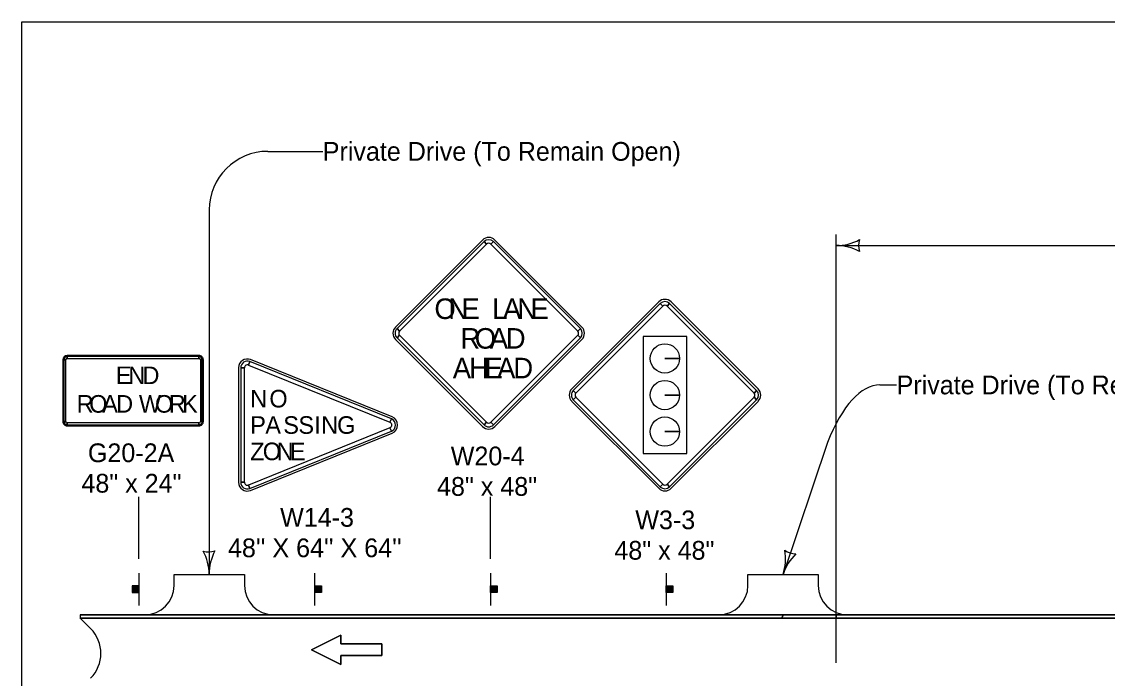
# Model space of a CAD drawing. Extents: x -2134934 to -2127057, y -2139046 to -2137036.
# Drawn here: x -2134934 to -2134008, y -2137596 to -2137036 of the extents above; entities that cross this region are included whole.
import ezdxf

# ---------------------------------------------------------------- set-up
doc = ezdxf.new("R2010")
doc.units = 0
for name, color, linetype in [('Barrier', 7, 'Continuous'), ('BridgeSuperStructureExisting', 7, 'Continuous'), ('Default', 7, 'Continuous'), ('DsnShtPlotIdentification', 7, 'Continuous'), ('DsnShtPlotShape', 7, 'Continuous')]:
    doc.layers.add(name, color=color, linetype=linetype)

msp = doc.modelspace()

# ---------------------------------------------------------------- linework, layer by layer
at = {"layer": 'Barrier'}
for p, q in [((-2134541.21, -2137222.31), (-2134615.45, -2137296.56)), ((-2134539.88, -2137223.64), (-2134537.67, -2137225.85)), ((-2134534.14, -2137225.85), (-2134531.93, -2137223.64)), ((-2134456.35, -2137296.56), (-2134530.6, -2137222.31)), ((-2134390.77, -2137275.12), (-2134465.02, -2137349.37)), ((-2134389.45, -2137276.45), (-2134387.24, -2137278.66)), ((-2134383.7, -2137278.66), (-2134381.49, -2137276.45)), ((-2134305.92, -2137349.37), (-2134380.17, -2137275.12)), ((-2134611.92, -2137300.09), (-2134614.13, -2137297.88)), ((-2134457.68, -2137297.88), (-2134459.89, -2137300.09)), ((-2134615.45, -2137307.16), (-2134541.21, -2137381.41)), ((-2134614.13, -2137305.84), (-2134611.92, -2137303.63)), ((-2134530.6, -2137381.41), (-2134456.35, -2137307.16)), ((-2134459.89, -2137303.63), (-2134457.68, -2137305.84)), ((-2134899.41, -2137324.64), (-2134899.41, -2137377.14)), ((-2134898.48, -2137324.64), (-2134896.91, -2137324.64)), ((-2134783.16, -2137320.89), (-2134895.66, -2137320.89)), ((-2134895.66, -2137323.39), (-2134895.66, -2137321.82)), ((-2134783.16, -2137321.82), (-2134783.16, -2137323.39)), ((-2134781.91, -2137324.64), (-2134780.35, -2137324.64)), ((-2134779.41, -2137377.14), (-2134779.41, -2137324.64)), ((-2134740.97, -2137329.01), (-2134739.8, -2137326.11)), ((-2134618.27, -2137373.25), (-2134739.1, -2137324.37)), ((-2134373.06, -2137323.34), (-2134385.56, -2137323.34)), ((-2134385.56, -2137323.34), (-2134373.06, -2137323.34)), ((-2134749.41, -2137331.32), (-2134749.41, -2137429.07)), ((-2134747.53, -2137331.32), (-2134744.41, -2137331.32)), ((-2134461.48, -2137352.9), (-2134463.69, -2137350.69)), ((-2134463.69, -2137358.65), (-2134461.48, -2137356.44)), ((-2134373.06, -2137354.59), (-2134385.56, -2137354.59)), ((-2134385.56, -2137354.59), (-2134373.06, -2137354.59)), ((-2134307.25, -2137350.69), (-2134309.45, -2137352.9)), ((-2134309.45, -2137356.44), (-2134307.25, -2137358.65)), ((-2134465.02, -2137359.98), (-2134390.77, -2137434.22)), ((-2134380.17, -2137434.22), (-2134305.92, -2137359.98)), ((-2134618.98, -2137374.98), (-2134620.15, -2137377.88)), ((-2134896.91, -2137377.14), (-2134898.48, -2137377.14)), ((-2134895.66, -2137379.95), (-2134895.66, -2137378.39)), ((-2134895.66, -2137380.89), (-2134783.16, -2137380.89)), ((-2134783.16, -2137378.39), (-2134783.16, -2137379.95)), ((-2134780.35, -2137377.14), (-2134781.91, -2137377.14)), ((-2134620.15, -2137382.52), (-2134618.98, -2137385.41)), ((-2134537.67, -2137377.87), (-2134539.88, -2137380.08)), ((-2134531.93, -2137380.08), (-2134534.14, -2137377.87)), ((-2134739.1, -2137436.03), (-2134618.27, -2137387.15)), ((-2134373.06, -2137385.84), (-2134385.56, -2137385.84)), ((-2134385.56, -2137385.84), (-2134373.06, -2137385.84)), ((-2134744.41, -2137429.07), (-2134747.53, -2137429.07)), ((-2134387.24, -2137430.69), (-2134389.45, -2137432.9)), ((-2134381.49, -2137432.9), (-2134383.7, -2137430.69)), ((-2134739.8, -2137434.29), (-2134740.97, -2137431.39))]:
    msp.add_line(p, q, dxfattribs=at)
for points in [[(-2134539.88, -2137223.64), (-2134614.13, -2137297.88), (-2134611.92, -2137300.09), (-2134537.67, -2137225.85), (-2134539.88, -2137223.64)], [(-2134457.68, -2137297.88), (-2134531.93, -2137223.64), (-2134534.14, -2137225.85), (-2134459.89, -2137300.09), (-2134457.68, -2137297.88)], [(-2134389.45, -2137276.45), (-2134463.69, -2137350.69), (-2134461.48, -2137352.9), (-2134387.24, -2137278.66), (-2134389.45, -2137276.45)], [(-2134307.25, -2137350.69), (-2134381.49, -2137276.45), (-2134383.7, -2137278.66), (-2134309.45, -2137352.9), (-2134307.25, -2137350.69)], [(-2134614.13, -2137305.84), (-2134539.88, -2137380.08), (-2134537.67, -2137377.87), (-2134611.92, -2137303.63), (-2134614.13, -2137305.84)], [(-2134531.93, -2137380.08), (-2134457.68, -2137305.84), (-2134459.89, -2137303.63), (-2134534.14, -2137377.87), (-2134531.93, -2137380.08)], [(-2134366.74, -2137304.73), (-2134404.2, -2137304.73), (-2134404.2, -2137404.62), (-2134366.74, -2137404.62), (-2134366.74, -2137304.73)], [(-2134898.48, -2137324.64), (-2134898.48, -2137377.14), (-2134896.91, -2137377.14), (-2134896.91, -2137324.64), (-2134898.48, -2137324.64)], [(-2134783.16, -2137321.82), (-2134895.66, -2137321.82), (-2134895.66, -2137323.39), (-2134783.16, -2137323.39), (-2134783.16, -2137321.82)], [(-2134780.35, -2137377.14), (-2134780.35, -2137324.64), (-2134781.91, -2137324.64), (-2134781.91, -2137377.14), (-2134780.35, -2137377.14)], [(-2134618.98, -2137374.98), (-2134739.8, -2137326.11), (-2134740.97, -2137329.01), (-2134620.15, -2137377.88), (-2134618.98, -2137374.98)], [(-2134747.53, -2137331.32), (-2134747.53, -2137429.07), (-2134744.41, -2137429.07), (-2134744.41, -2137331.32), (-2134747.53, -2137331.32)], [(-2134463.69, -2137358.65), (-2134389.45, -2137432.9), (-2134387.24, -2137430.69), (-2134461.48, -2137356.44), (-2134463.69, -2137358.65)], [(-2134381.49, -2137432.9), (-2134307.25, -2137358.65), (-2134309.45, -2137356.44), (-2134383.7, -2137430.69), (-2134381.49, -2137432.9)], [(-2134895.66, -2137379.95), (-2134783.16, -2137379.95), (-2134783.16, -2137378.39), (-2134895.66, -2137378.39), (-2134895.66, -2137379.95)], [(-2134739.8, -2137434.29), (-2134618.98, -2137385.41), (-2134620.15, -2137382.52), (-2134740.97, -2137431.39), (-2134739.8, -2137434.29)]]:
    msp.add_lwpolyline(points, close=True, dxfattribs=at)
for centre in [(-2134385.56, -2137323.34), (-2134385.56, -2137354.59), (-2134385.56, -2137385.84)]:
    msp.add_circle(centre, 12.5, dxfattribs=at)
for centre, radius, start, end in [((-2134535.9, -2137227.61), 7.5, 44.99999, 134.99974), ((-2134535.9, -2137227.61), 5.62, 44.99999, 134.99974), ((-2134535.9, -2137227.61), 2.5, 44.99999, 134.99974), ((-2134385.47, -2137280.43), 7.5, 44.99999, 134.99974), ((-2134385.47, -2137280.43), 5.62, 44.99999, 134.99974), ((-2134385.47, -2137280.43), 2.5, 44.99999, 134.99974), ((-2134610.15, -2137301.86), 7.5, 134.99974, 224.99995), ((-2134610.15, -2137301.86), 5.62, 134.99974, 224.99995), ((-2134610.15, -2137301.86), 2.5, 134.99974, 224.99995), ((-2134461.66, -2137301.86), 2.5, 315.00016, 44.9998), ((-2134461.66, -2137301.86), 5.62, 315.00016, 44.9998), ((-2134461.66, -2137301.86), 7.5, 315.00016, 44.9998), ((-2134895.66, -2137324.64), 3.75, 90.00021, 179.99985), ((-2134895.66, -2137324.64), 2.81, 90.00021, 179.99985), ((-2134895.66, -2137324.64), 1.25, 90.00021, 179.99985), ((-2134783.16, -2137324.64), 3.75, 0, 90.00021), ((-2134783.16, -2137324.64), 2.81, 0, 90.00021), ((-2134783.16, -2137324.64), 1.25, 0, 90.00021), ((-2134741.91, -2137331.32), 7.5, 67.97571, 179.99985), ((-2134741.91, -2137331.32), 5.62, 67.97571, 179.99985), ((-2134741.91, -2137331.32), 2.5, 67.97571, 179.99985), ((-2134459.72, -2137354.67), 7.5, 134.99974, 224.99995), ((-2134459.72, -2137354.67), 5.62, 134.99974, 224.99995), ((-2134459.72, -2137354.67), 2.5, 134.99974, 224.99995), ((-2134311.22, -2137354.67), 2.5, 315.00016, 44.9998), ((-2134311.22, -2137354.67), 5.62, 315.00016, 44.9998), ((-2134311.22, -2137354.67), 7.5, 315.00016, 44.9998), ((-2134621.09, -2137380.2), 5.62, 292.02456, 67.97541), ((-2134621.09, -2137380.2), 7.5, 292.02456, 67.97598), ((-2134895.66, -2137377.14), 3.75, 179.99985, 270.00006), ((-2134895.66, -2137377.14), 2.81, 179.99985, 270.00006), ((-2134895.66, -2137377.14), 1.25, 179.99985, 270.00006), ((-2134783.16, -2137377.14), 3.75, 270.00006, 0.00027), ((-2134783.16, -2137377.14), 2.81, 270.00006, 0.00027), ((-2134783.16, -2137377.14), 1.25, 270.00006, 0.00027), ((-2134621.09, -2137380.2), 2.5, 292.02456, 67.97541), ((-2134535.9, -2137376.11), 7.5, 224.99995, 315.00016), ((-2134535.9, -2137376.11), 5.62, 224.99995, 315.00016), ((-2134535.9, -2137376.11), 2.5, 224.99995, 315.00016), ((-2134741.91, -2137429.07), 7.5, 179.99985, 292.02456), ((-2134741.91, -2137429.07), 5.62, 179.99985, 292.02456), ((-2134741.91, -2137429.07), 2.5, 179.99985, 292.02456), ((-2134385.47, -2137428.92), 2.5, 224.99995, 315.00016), ((-2134385.47, -2137428.92), 7.5, 224.99995, 315.00016), ((-2134385.47, -2137428.92), 5.62, 224.99995, 315.00016)]:
    msp.add_arc(centre, radius, start, end, dxfattribs=at)
at = {"layer": 'BridgeSuperStructureExisting'}
for p, q in [((-2134724.38, -2137146.61), (-2134677.51, -2137146.61)), ((-2134774.38, -2137196.61), (-2134774.38, -2137507.67)), ((-2134239.44, -2137583.23), (-2134239.44, -2137217.69)), ((-2134239.44, -2137226.98), (-2133580.02, -2137226.98)), ((-2134202.01, -2137345.99), (-2134187.79, -2137345.99)), ((-2134246.74, -2137395.12), (-2134284.66, -2137507.67)), ((-2134834.44, -2137494.5), (-2134834.44, -2137441.62)), ((-2134534.44, -2137494.5), (-2134534.44, -2137441.62)), ((-2134834.44, -2137506.66), (-2134834.44, -2137534.16)), ((-2134684.44, -2137506.66), (-2134684.44, -2137534.16)), ((-2134534.44, -2137506.66), (-2134534.44, -2137534.16)), ((-2134384.44, -2137506.66), (-2134384.44, -2137534.16)), ((-2134839.77, -2137517.52), (-2134839.77, -2137523.11)), ((-2134839.45, -2137523.11), (-2134839.45, -2137517.52)), ((-2134839.22, -2137517.52), (-2134839.22, -2137523.11)), ((-2134838.9, -2137523.11), (-2134838.9, -2137517.52)), ((-2134838.68, -2137517.52), (-2134838.7, -2137523.11)), ((-2134838.27, -2137523.11), (-2134838.25, -2137517.52)), ((-2134838.04, -2137517.52), (-2134838.04, -2137523.11)), ((-2134837.61, -2137523.11), (-2134837.61, -2137517.52)), ((-2134837.24, -2137517.52), (-2134837.24, -2137523.11)), ((-2134836.92, -2137523.11), (-2134836.9, -2137517.52)), ((-2134836.69, -2137517.52), (-2134836.69, -2137523.11)), ((-2134836.43, -2137523.11), (-2134836.43, -2137517.52)), ((-2134836.09, -2137517.52), (-2134836.09, -2137523.11)), ((-2134835.89, -2137523.11), (-2134835.89, -2137517.52)), ((-2134835.66, -2137517.52), (-2134835.66, -2137523.11)), ((-2134835.4, -2137523.11), (-2134835.4, -2137517.52)), ((-2134835.14, -2137517.52), (-2134835.14, -2137523.11)), ((-2134834.85, -2137523.11), (-2134834.85, -2137517.52)), ((-2134684.03, -2137523.11), (-2134684.03, -2137517.52)), ((-2134683.75, -2137517.52), (-2134683.75, -2137523.11)), ((-2134683.48, -2137523.11), (-2134683.48, -2137517.52)), ((-2134683.22, -2137517.52), (-2134683.22, -2137523.11)), ((-2134683, -2137523.11), (-2134683, -2137517.52)), ((-2134682.79, -2137517.52), (-2134682.79, -2137523.11)), ((-2134682.45, -2137523.11), (-2134682.45, -2137517.52)), ((-2134682.19, -2137517.52), (-2134682.19, -2137523.11)), ((-2134681.97, -2137523.11), (-2134681.98, -2137517.52)), ((-2134681.65, -2137517.52), (-2134681.65, -2137523.11)), ((-2134681.27, -2137523.11), (-2134681.27, -2137517.52)), ((-2134680.84, -2137517.52), (-2134680.84, -2137523.11)), ((-2134680.62, -2137523.11), (-2134680.63, -2137517.52)), ((-2134680.2, -2137517.52), (-2134680.18, -2137523.11)), ((-2134679.98, -2137523.11), (-2134679.98, -2137517.52)), ((-2134679.66, -2137517.52), (-2134679.66, -2137523.11)), ((-2134679.43, -2137523.11), (-2134679.43, -2137517.52)), ((-2134679.12, -2137517.52), (-2134679.12, -2137523.11)), ((-2134534.03, -2137523.11), (-2134534.03, -2137517.52)), ((-2134533.75, -2137517.52), (-2134533.75, -2137523.11)), ((-2134533.48, -2137523.11), (-2134533.48, -2137517.52)), ((-2134533.22, -2137517.52), (-2134533.22, -2137523.11)), ((-2134533, -2137523.11), (-2134533, -2137517.52)), ((-2134532.79, -2137517.52), (-2134532.79, -2137523.11)), ((-2134532.45, -2137523.11), (-2134532.45, -2137517.52)), ((-2134532.19, -2137517.52), (-2134532.19, -2137523.11)), ((-2134531.97, -2137523.11), (-2134531.98, -2137517.52)), ((-2134531.65, -2137517.52), (-2134531.65, -2137523.11)), ((-2134531.27, -2137523.11), (-2134531.27, -2137517.52)), ((-2134530.84, -2137517.52), (-2134530.84, -2137523.11)), ((-2134530.62, -2137523.11), (-2134530.63, -2137517.52)), ((-2134530.2, -2137517.52), (-2134530.18, -2137523.11)), ((-2134529.98, -2137523.11), (-2134529.98, -2137517.52)), ((-2134529.66, -2137517.52), (-2134529.66, -2137523.11)), ((-2134529.43, -2137523.11), (-2134529.43, -2137517.52)), ((-2134529.12, -2137517.52), (-2134529.12, -2137523.11)), ((-2134384.03, -2137523.11), (-2134384.03, -2137517.52)), ((-2134383.75, -2137517.52), (-2134383.75, -2137523.11)), ((-2134383.48, -2137523.11), (-2134383.48, -2137517.52)), ((-2134383.22, -2137517.52), (-2134383.22, -2137523.11)), ((-2134383, -2137523.11), (-2134383, -2137517.52)), ((-2134382.79, -2137517.52), (-2134382.79, -2137523.11)), ((-2134382.45, -2137523.11), (-2134382.45, -2137517.52)), ((-2134382.19, -2137517.52), (-2134382.19, -2137523.11)), ((-2134381.97, -2137523.11), (-2134381.98, -2137517.52)), ((-2134381.65, -2137517.52), (-2134381.65, -2137523.11)), ((-2134381.27, -2137523.11), (-2134381.27, -2137517.52)), ((-2134380.84, -2137517.52), (-2134380.84, -2137523.11)), ((-2134380.62, -2137523.11), (-2134380.63, -2137517.52)), ((-2134380.2, -2137517.52), (-2134380.18, -2137523.11)), ((-2134379.98, -2137523.11), (-2134379.98, -2137517.52)), ((-2134379.66, -2137517.52), (-2134379.66, -2137523.11)), ((-2134379.43, -2137523.11), (-2134379.43, -2137517.52)), ((-2134379.12, -2137517.52), (-2134379.12, -2137523.11)), ((-2134875.66, -2137553.94), (-2134884.44, -2137545.16)), ((-2133574.44, -2137545.16), (-2134884.44, -2137545.16)), ((-2134884.44, -2137545.16), (-2134875.65, -2137553.95)), ((-2134719.38, -2137542.16), (-2134829.38, -2137542.16)), ((-2134229.66, -2137542.16), (-2134339.66, -2137542.16))]:
    msp.add_line(p, q, dxfattribs=at)
for points in [[(-2134804.38, -2137517.16), (-2134804.38, -2137507.67), (-2134744.38, -2137507.67), (-2134744.38, -2137517.16)], [(-2134314.66, -2137517.16), (-2134314.66, -2137507.67), (-2134254.66, -2137507.67), (-2134254.66, -2137517.16)], [(-2134662.04, -2137577), (-2134662.04, -2137584.5), (-2134687.04, -2137572), (-2134662.04, -2137559.5), (-2134662.04, -2137567), (-2134627.04, -2137567), (-2134627.04, -2137577), (-2134662.04, -2137577)]]:
    msp.add_lwpolyline(points, dxfattribs=at)
for points in [[(-2134834.54, -2137523.11), (-2134834.54, -2137517.48), (-2134840.16, -2137517.48), (-2134840.16, -2137523.11)], [(-2134684.35, -2137523.11), (-2134684.35, -2137517.48), (-2134678.72, -2137517.48), (-2134678.72, -2137523.11)], [(-2134534.35, -2137523.11), (-2134534.35, -2137517.48), (-2134528.72, -2137517.48), (-2134528.72, -2137523.11)], [(-2134384.35, -2137523.11), (-2134384.35, -2137517.48), (-2134378.72, -2137517.48), (-2134378.72, -2137523.11)], [(-2134627.04, -2137577), (-2134627.04, -2137567), (-2134662.04, -2137567), (-2134662.04, -2137559.5), (-2134687.04, -2137572), (-2134662.04, -2137584.5), (-2134662.04, -2137577)]]:
    msp.add_lwpolyline(points, close=True, dxfattribs=at)
for centre, radius, start, end in [((-2134724.38, -2137196.61), 50, 90, 180), ((-2134829.38, -2137517.16), 25, 270, 0), ((-2134719.38, -2137517.16), 25, 180, 270), ((-2134339.66, -2137517.16), 25, 270, 360), ((-2134229.66, -2137517.16), 25, 180, 270), ((-2134896.87, -2137575.16), 30, 315, 45), ((-2134896.87, -2137575.16), 30, 315, 45)]:
    msp.add_arc(centre, radius, start, end, dxfattribs=at)
msp.add_ellipse((-2134202.01, -2137558.92), major_axis=(0, 212.93), ratio=0.328743, start_param=0, end_param=0.693162, dxfattribs=at)
at = {"layer": 'Default'}
msp.add_lwpolyline([(-2134934.44, -2137035.95), (-2131799.45, -2137035.95), (-2131799.45, -2139045.94), (-2134934.44, -2139045.94)], close=True, dxfattribs=at)
at = {"layer": 'DsnShtPlotIdentification'}
for p, q in [((-2134884.44, -2137542.16), (-2134884.44, -2137545.16)), ((-2134884.44, -2137542.16), (-2134884.44, -2137545.16)), ((-2134284.66, -2137542.16), (-2134884.44, -2137542.16)), ((-2134884.44, -2137545.16), (-2134285.86, -2137545.16)), ((-2134284.66, -2137542.16), (-2134285.86, -2137545.16)), ((-2134285.86, -2137545.16), (-2134284.66, -2137542.16)), ((-2134285.86, -2137545.16), (-2134239.44, -2137545.16)), ((-2134239.44, -2137542.16), (-2134284.66, -2137542.16)), ((-2133766.47, -2137542.16), (-2134239.44, -2137542.16)), ((-2134239.44, -2137542.16), (-2134239.44, -2137545.16)), ((-2134239.44, -2137545.16), (-2134239.44, -2137542.16)), ((-2134239.44, -2137545.16), (-2133764.3, -2137545.16))]:
    msp.add_line(p, q, dxfattribs=at)
for points in [[(-2134884.86, -2137545.16), (-2133574.86, -2137545.16)], [(-2134884.44, -2137542.16), (-2133574.44, -2137542.16)], [(-2134884.44, -2137545.16), (-2133574.44, -2137545.16)]]:
    msp.add_lwpolyline(points, dxfattribs=at)
at = {"layer": 'DsnShtPlotShape'}
for centre, radius, start, end in [((-2134239.44, -2137184.48), 42.5, 270, 298.07249), ((-2134239.44, -2137269.48), 42.5, 61.92751, 90), ((-2134203.81, -2137226.98), 16.42, 162.26665, 197.73335), ((-2134774.82, -2137472.04), 16.42, 252.97281, 288.43951), ((-2134816.87, -2137508.19), 42.5, 0.70616, 28.77865), ((-2134731.88, -2137507.15), 42.5, 152.63367, 180.70616), ((-2134325.1, -2137494.6), 42.5, 342.08492, 10.15741), ((-2134244.23, -2137520.74), 42.5, 134.01243, 162.08492), ((-2134273.7, -2137473.76), 16.42, 234.35157, 269.81827)]:
    msp.add_arc(centre, radius, start, end, dxfattribs=at)

# ---------------------------------------------------------------- texts
at = {"layer": 'Barrier'}
for s, height, p in [('O', 17.5, (-2134582.19, -2137289.67)), ('N', 17.5, (-2134570.41, -2137289.67)), ('E', 17.5, (-2134559.19, -2137289.67)), ('L', 17.5, (-2134532.94, -2137289.67)), ('A', 17.5, (-2134523.74, -2137289.67)), ('N', 17.5, (-2134511.47, -2137289.67)), ('E', 17.5, (-2134500.24, -2137289.67)), ('R', 17.5, (-2134560.08, -2137314.98)), ('O', 17.5, (-2134547.79, -2137314.98)), ('A', 17.5, (-2134534.95, -2137314.98)), ('D', 17.5, (-2134521.3, -2137314.98)), ('A', 17.5, (-2134566.52, -2137340.3)), ('H', 17.5, (-2134552.65, -2137340.3)), ('E', 17.5, (-2134539.44, -2137340.3)), ('A', 17.5, (-2134528.72, -2137340.3)), ('D', 17.5, (-2134514.86, -2137340.3)), ('E', 15, (-2134854.09, -2137345.26)), ('N', 15, (-2134843.47, -2137345.26)), ('D', 15, (-2134831.38, -2137345.26)), ('R', 15, (-2134887.55, -2137369.64)), ('O', 15, (-2134876.87, -2137369.64)), ('A', 15, (-2134865.71, -2137369.64)), ('D', 15, (-2134853.85, -2137369.64)), ('W', 15, (-2134834.4, -2137369.64)), ('O', 15, (-2134820.67, -2137369.64)), ('R', 15, (-2134808.9, -2137369.64)), ('K', 15, (-2134797.6, -2137369.64)), ('N', 15, (-2134739.44, -2137365.2)), ('O', 15, (-2134723.1, -2137365.2)), ('P', 15, (-2134739.44, -2137387.7)), ('A', 15, (-2134726.55, -2137387.7)), ('S', 15, (-2134711.2, -2137387.7)), ('S', 15, (-2134698.31, -2137387.7)), ('I', 15, (-2134684.71, -2137387.7)), ('N', 15, (-2134678.85, -2137387.7)), ('G', 15, (-2134665.26, -2137387.7)), ('G20-2A', 16, (-2134877.94, -2137411.89)), ('Z', 15, (-2134739.44, -2137410.2)), ('O', 15, (-2134728.7, -2137410.2)), ('N', 15, (-2134716.87, -2137410.2)), ('E', 15, (-2134705.51, -2137410.2)), ('W20-4', 16, (-2134568.27, -2137414.61)), ('48" x 24"', 16, (-2134883.48, -2137437.89)), ('48" x 48"', 16, (-2134579.97, -2137440.61)), ('W14-3', 16, (-2134713.9, -2137467.03)), ('W3-3', 16, (-2134410.76, -2137469.14)), ("48'' X 64'' X 64''", 16, (-2134758.39, -2137493.03)), ('48" x 48"', 16, (-2134428.64, -2137495.14))]:
    msp.add_text(s, height=height, dxfattribs=at).set_placement(p)
at = {"layer": 'BridgeSuperStructureExisting'}
for p in [(-2134677.51, -2137154.61), (-2134187.79, -2137353.99)]:
    msp.add_text('Private Drive (To Remain Open)', height=16, dxfattribs=at).set_placement(p)

doc.saveas('drawing.dxf')
